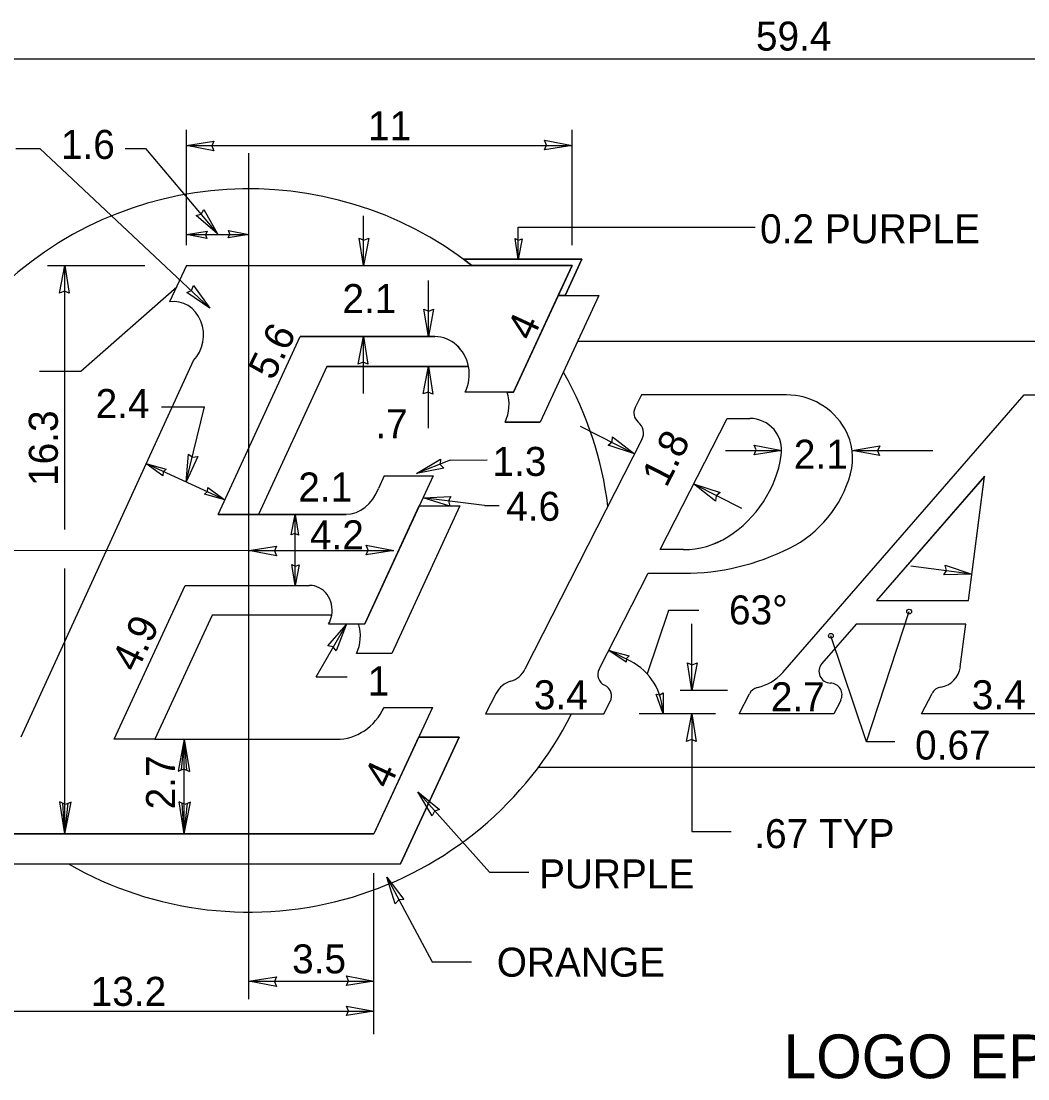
# Model space of a CAD drawing. Extents: x 10268197 to 10269179, y 2141503 to 2142677.
# Drawn here: x 10268684.39 to 10268704.22, y 2142077.2 to 2142098.03 of the extents above; entities that cross this region are included whole.
import ezdxf

# ---------------------------------------------------------------- set-up
doc = ezdxf.new("R2010")
doc.units = 0
doc.layers.add('Default', color=7, linetype='Continuous')
doc.layers.add('TextDetails', color=7, linetype='Continuous')

msp = doc.modelspace()

# ---------------------------------------------------------------- linework, layer by layer
at = {"layer": 'Default'}
for p, q in [((10268679.858, 2142097.295), (10268720.621, 2142097.295)), ((10268687.644, 2142093.619), (10268687.644, 2142095.89)), ((10268695.243, 2142093.619), (10268695.243, 2142095.89)), ((10268687.644, 2142095.584), (10268695.243, 2142095.584)), ((10268686.439, 2142095.525), (10268686.841, 2142095.525)), ((10268686.841, 2142095.525), (10268688.255, 2142093.844)), ((10268688.878, 2142087.607), (10268688.878, 2142095.433)), ((10268691.134, 2142093.218), (10268691.134, 2142094.201)), ((10268694.183, 2142093.342), (10268694.183, 2142093.975)), ((10268694.183, 2142093.975), (10268698.851, 2142093.975)), ((10268687.644, 2142093.831), (10268688.878, 2142093.831)), ((10268693.268, 2142093.218), (10268693.105, 2142093.342)), ((10268693.105, 2142093.342), (10268695.436, 2142093.342)), ((10268693.105, 2142093.342), (10268695.436, 2142093.342)), ((10268695.436, 2142093.342), (10268695.107, 2142092.629)), ((10268695.436, 2142093.342), (10268695.107, 2142092.629)), ((10268684.906, 2142093.218), (10268686.824, 2142093.218)), ((10268685.25, 2142088.019), (10268685.25, 2142093.218)), ((10268687.644, 2142093.218), (10268687.315, 2142092.505)), ((10268687.644, 2142093.218), (10268695.243, 2142093.218)), ((10268695.243, 2142093.218), (10268693.268, 2142093.218)), ((10268695.243, 2142093.218), (10268694.091, 2142090.725)), ((10268694.971, 2142092.629), (10268695.243, 2142093.218)), ((10268692.412, 2142091.819), (10268692.412, 2142092.925)), ((10268685.565, 2142091.137), (10268687.454, 2142092.8)), ((10268694.091, 2142090.725), (10268694.971, 2142092.629)), ((10268695.77, 2142092.629), (10268694.617, 2142090.135)), ((10268695.77, 2142092.629), (10268694.617, 2142090.135)), ((10268694.971, 2142092.629), (10268695.77, 2142092.629)), ((10268694.971, 2142092.629), (10268695.77, 2142092.629)), ((10268694.971, 2142092.629), (10268695.77, 2142092.629)), ((10268695.107, 2142092.629), (10268694.971, 2142092.629)), ((10268688.27, 2142088.318), (10268689.885, 2142091.819)), ((10268688.27, 2142088.318), (10268689.885, 2142091.819)), ((10268688.27, 2142088.318), (10268689.885, 2142091.819)), ((10268689.885, 2142091.819), (10268692.542, 2142091.819)), ((10268689.885, 2142091.819), (10268692.542, 2142091.819)), ((10268690.384, 2142091.819), (10268689.885, 2142091.819)), ((10268689.885, 2142091.819), (10268692.542, 2142091.819)), ((10268689.885, 2142091.819), (10268692.542, 2142091.819)), ((10268692.542, 2142091.819), (10268690.384, 2142091.819)), ((10268691.134, 2142090.698), (10268691.134, 2142091.819)), ((10268720.621, 2142091.721), (10268695.35, 2142091.721)), ((10268684.389, 2142083.937), (10268687.785, 2142091.349)), ((10268690.414, 2142091.229), (10268689.068, 2142088.318)), ((10268690.414, 2142091.229), (10268689.068, 2142088.318)), ((10268690.414, 2142091.229), (10268689.068, 2142088.318)), ((10268693.204, 2142091.229), (10268690.414, 2142091.229)), ((10268690.414, 2142091.229), (10268693.204, 2142091.229)), ((10268693.204, 2142091.229), (10268690.414, 2142091.229)), ((10268693.204, 2142091.229), (10268690.912, 2142091.229)), ((10268692.412, 2142090.014), (10268692.412, 2142091.229)), ((10268684.749, 2142091.137), (10268685.565, 2142091.137)), ((10268694.091, 2142090.725), (10268693.14, 2142090.725)), ((10268693.964, 2142090.725), (10268694.091, 2142090.725)), ((10268696.612, 2142090.673), (10268696.485, 2142090.424)), ((10268699.465, 2142090.673), (10268696.612, 2142090.673)), ((10268699.394, 2142085.202), (10268704.15, 2142090.673)), ((10268704.15, 2142090.673), (10268704.987, 2142090.673)), ((10268687.155, 2142090.434), (10268688, 2142090.434)), ((10268687.637, 2142088.957), (10268688, 2142090.434)), ((10268696.978, 2142087.623), (10268698.296, 2142090.208)), ((10268696.978, 2142087.623), (10268698.296, 2142090.207)), ((10268698.296, 2142090.208), (10268698.745, 2142090.208)), ((10268698.296, 2142090.207), (10268698.745, 2142090.207)), ((10268693.922, 2142090.135), (10268694.617, 2142090.135)), ((10268694.617, 2142090.135), (10268693.922, 2142090.135)), ((10268695.402, 2142090.057), (10268696.476, 2142089.509)), ((10268696.62, 2142089.793), (10268694.315, 2142085.267)), ((10268698.269, 2142089.579), (10268699.373, 2142089.579)), ((10268700.76, 2142089.579), (10268702.349, 2142089.579)), ((10268688.402, 2142088.604), (10268686.848, 2142089.32)), ((10268692.842, 2142089.387), (10268692.177, 2142089.122)), ((10268692.842, 2142089.387), (10268693.568, 2142089.391)), ((10268692.507, 2142089.075), (10268691.162, 2142086.163)), ((10268691.542, 2142089.075), (10268691.428, 2142088.827)), ((10268691.542, 2142089.075), (10268692.507, 2142089.075)), ((10268697.639, 2142088.918), (10268698.579, 2142088.439)), ((10268703.37, 2142089.067), (10268701.243, 2142086.621)), ((10268703.37, 2142089.066), (10268701.243, 2142086.621)), ((10268703.051, 2142086.621), (10268703.37, 2142089.067)), ((10268703.051, 2142086.621), (10268703.37, 2142089.066)), ((10268691.162, 2142086.163), (10268692.234, 2142088.485)), ((10268693.033, 2142088.485), (10268691.69, 2142085.575)), ((10268693.033, 2142088.485), (10268691.69, 2142085.575)), ((10268692.234, 2142088.485), (10268693.033, 2142088.485)), ((10268692.234, 2142088.485), (10268693.033, 2142088.485)), ((10268693.517, 2142088.494), (10268692.307, 2142088.643)), ((10268693.517, 2142088.494), (10268693.805, 2142088.495)), ((10268688.27, 2142088.318), (10268690.791, 2142088.318)), ((10268690.791, 2142088.318), (10268688.27, 2142088.318)), ((10268689.068, 2142088.318), (10268688.27, 2142088.318)), ((10268688.27, 2142088.318), (10268690.791, 2142088.318)), ((10268690.791, 2142088.318), (10268688.27, 2142088.318)), ((10268688.769, 2142088.318), (10268689.569, 2142088.318)), ((10268689.79, 2142086.919), (10268689.79, 2142088.318)), ((10268688.878, 2142087.607), (10268681.752, 2142087.596)), ((10268688.878, 2142078.769), (10268688.878, 2142087.607)), ((10268688.878, 2142087.607), (10268691.729, 2142087.607)), ((10268697.439, 2142087.623), (10268696.978, 2142087.623)), ((10268697.439, 2142087.623), (10268696.978, 2142087.623)), ((10268685.25, 2142082.021), (10268685.25, 2142087.253)), ((10268703.12, 2142087.142), (10268701.916, 2142087.298)), ((10268695.777, 2142085.267), (10268696.741, 2142087.157)), ((10268696.741, 2142087.157), (10268697.439, 2142087.157)), ((10268686.222, 2142083.887), (10268687.622, 2142086.919)), ((10268686.222, 2142083.887), (10268687.622, 2142086.919)), ((10268687.622, 2142086.919), (10268690.073, 2142086.919)), ((10268687.622, 2142086.919), (10268690.073, 2142086.919)), ((10268701.243, 2142086.621), (10268703.051, 2142086.621)), ((10268701.243, 2142086.621), (10268703.051, 2142086.621)), ((10268697.144, 2142086.422), (10268696.722, 2142085.177)), ((10268697.743, 2142086.422), (10268697.144, 2142086.422)), ((10268701.046, 2142083.836), (10268701.886, 2142086.402)), ((10268688.152, 2142086.329), (10268687.021, 2142083.887)), ((10268688.152, 2142086.329), (10268687.021, 2142083.887)), ((10268690.508, 2142086.329), (10268688.152, 2142086.329)), ((10268690.508, 2142086.329), (10268688.152, 2142086.329)), ((10268690.201, 2142085.115), (10268690.793, 2142086.14)), ((10268690.447, 2142086.163), (10268691.162, 2142086.163)), ((10268691.037, 2142086.163), (10268691.162, 2142086.163)), ((10268697.605, 2142084.851), (10268697.605, 2142086.163)), ((10268700.84, 2142086.154), (10268700.165, 2142085.378)), ((10268703.003, 2142086.154), (10268700.84, 2142086.154)), ((10268702.893, 2142085.314), (10268703.003, 2142086.154)), ((10268701.046, 2142083.836), (10268700.342, 2142085.926)), ((10268691.69, 2142085.575), (10268690.994, 2142085.575)), ((10268691.69, 2142085.575), (10268690.994, 2142085.575)), ((10268696.396, 2142085.423), (10268695.969, 2142085.642)), ((10268690.201, 2142085.115), (10268690.809, 2142085.115)), ((10268693.748, 2142084.796), (10268693.539, 2142084.385)), ((10268698.304, 2142084.851), (10268697.372, 2142084.851)), ((10268698.536, 2142084.385), (10268698.739, 2142084.784)), ((10268702.13, 2142084.385), (10268702.337, 2142084.789)), ((10268695.867, 2142084.385), (10268695.994, 2142084.634)), ((10268700.538, 2142084.654), (10268700.4, 2142084.385)), ((10268692.493, 2142084.516), (10268691.34, 2142082.021)), ((10268691.542, 2142084.516), (10268692.493, 2142084.516)), ((10268693.539, 2142084.385), (10268695.867, 2142084.385)), ((10268698.071, 2142084.386), (10268696.566, 2142084.386)), ((10268697.605, 2142084.386), (10268697.605, 2142082.07)), ((10268700.4, 2142084.385), (10268698.536, 2142084.385)), ((10268704.459, 2142084.385), (10268702.13, 2142084.385)), ((10268692.219, 2142083.926), (10268691.34, 2142082.021)), ((10268693.019, 2142083.926), (10268691.866, 2142081.431)), ((10268691.866, 2142081.431), (10268693.019, 2142083.926)), ((10268692.219, 2142083.926), (10268693.019, 2142083.926)), ((10268693.019, 2142083.926), (10268692.219, 2142083.926)), ((10268687.021, 2142083.887), (10268686.222, 2142083.887)), ((10268687.021, 2142083.887), (10268686.222, 2142083.887)), ((10268687.021, 2142083.887), (10268690.603, 2142083.887)), ((10268687.602, 2142083.887), (10268687.48, 2142083.258)), ((10268687.602, 2142083.887), (10268687.539, 2142083.283)), ((10268687.602, 2142082.021), (10268687.602, 2142083.887)), ((10268687.602, 2142083.887), (10268687.703, 2142083.254)), ((10268687.602, 2142083.887), (10268687.644, 2142083.281)), ((10268701.604, 2142083.836), (10268701.046, 2142083.836)), ((10268687.48, 2142083.258), (10268687.592, 2142083.305)), ((10268687.592, 2142083.305), (10268687.703, 2142083.254)), ((10268694.582, 2142083.337), (10268716.35, 2142083.337)), ((10268685.25, 2142082.021), (10268685.15, 2142082.653)), ((10268685.26, 2142082.603), (10268685.15, 2142082.653)), ((10268685.25, 2142082.021), (10268685.372, 2142082.649)), ((10268685.372, 2142082.649), (10268685.26, 2142082.603)), ((10268687.602, 2142082.021), (10268687.502, 2142082.653)), ((10268687.612, 2142082.603), (10268687.502, 2142082.653)), ((10268687.602, 2142082.021), (10268687.724, 2142082.649)), ((10268687.724, 2142082.649), (10268687.612, 2142082.603)), ((10268692.206, 2142082.851), (10268693.615, 2142081.271)), ((10268685.25, 2142082.021), (10268685.208, 2142082.626)), ((10268685.25, 2142082.021), (10268685.313, 2142082.625)), ((10268687.602, 2142082.021), (10268687.56, 2142082.626)), ((10268687.602, 2142082.021), (10268687.666, 2142082.625)), ((10268682.288, 2142082.021), (10268691.34, 2142082.021)), ((10268691.34, 2142082.021), (10268683.678, 2142082.021)), ((10268697.605, 2142082.07), (10268698.381, 2142082.07)), ((10268683.405, 2142081.431), (10268691.866, 2142081.431)), ((10268683.405, 2142081.431), (10268691.866, 2142081.431)), ((10268691.34, 2142078.077), (10268691.34, 2142081.246)), ((10268693.615, 2142081.271), (10268694.39, 2142081.271)), ((10268691.597, 2142081.169), (10268692.484, 2142079.502)), ((10268692.484, 2142079.502), (10268693.26, 2142079.502)), ((10268688.878, 2142079.12), (10268691.34, 2142079.12)), ((10268682.313, 2142078.528), (10268691.34, 2142078.528))]:
    msp.add_line(p, q, dxfattribs=at)
for points in [[(10268687.644, 2142095.584), (10268688.188, 2142095.67), (10268688.147, 2142095.577), (10268688.184, 2142095.48)], [(10268695.243, 2142095.584), (10268694.699, 2142095.499), (10268694.74, 2142095.592), (10268694.703, 2142095.688)], [(10268688.255, 2142093.844), (10268687.839, 2142094.205), (10268687.937, 2142094.234), (10268687.987, 2142094.325)], [(10268688.878, 2142093.831), (10268688.469, 2142093.767), (10268688.5, 2142093.836), (10268688.472, 2142093.909)], [(10268687.644, 2142093.831), (10268688.051, 2142093.895), (10268688.021, 2142093.825), (10268688.049, 2142093.753)], [(10268691.134, 2142093.218), (10268691.048, 2142093.762), (10268691.141, 2142093.721), (10268691.238, 2142093.758)], [(10268694.183, 2142093.342), (10268694.119, 2142093.75), (10268694.189, 2142093.719), (10268694.261, 2142093.748)], [(10268693.105, 2142093.342), (10268693.268, 2142093.218), (10268695.243, 2142093.218), (10268694.971, 2142092.629), (10268695.107, 2142092.629), (10268695.436, 2142093.342)], [(10268685.25, 2142093.218), (10268685.336, 2142092.674), (10268685.243, 2142092.715), (10268685.146, 2142092.678)], [(10268688.109, 2142092.378), (10268687.654, 2142092.688), (10268687.747, 2142092.728), (10268687.786, 2142092.824)], [(10268692.412, 2142091.819), (10268692.326, 2142092.363), (10268692.42, 2142092.322), (10268692.516, 2142092.359)], [(10268691.134, 2142091.819), (10268691.22, 2142091.275), (10268691.127, 2142091.316), (10268691.03, 2142091.279)], [(10268692.412, 2142091.229), (10268692.498, 2142090.685), (10268692.405, 2142090.726), (10268692.308, 2142090.689)], [(10268696.476, 2142089.509), (10268695.952, 2142089.68), (10268696.031, 2142089.745), (10268696.042, 2142089.848)], [(10268699.373, 2142089.579), (10268698.829, 2142089.493), (10268698.87, 2142089.587), (10268698.833, 2142089.683)], [(10268700.76, 2142089.579), (10268701.304, 2142089.665), (10268701.264, 2142089.572), (10268701.301, 2142089.475)], [(10268686.848, 2142089.32), (10268687.246, 2142089.208), (10268687.188, 2142089.157), (10268687.183, 2142089.08)], [(10268687.637, 2142088.957), (10268687.683, 2142089.506), (10268687.764, 2142089.444), (10268687.867, 2142089.457)], [(10268692.177, 2142089.122), (10268692.651, 2142089.403), (10268692.647, 2142089.301), (10268692.718, 2142089.225)], [(10268697.639, 2142088.918), (10268698.162, 2142088.747), (10268698.083, 2142088.683), (10268698.072, 2142088.58)], [(10268688.402, 2142088.604), (10268688.004, 2142088.717), (10268688.061, 2142088.767), (10268688.066, 2142088.845)], [(10268692.307, 2142088.643), (10268692.857, 2142088.67), (10268692.806, 2142088.581), (10268692.833, 2142088.481)], [(10268689.79, 2142088.318), (10268689.854, 2142087.91), (10268689.784, 2142087.941), (10268689.712, 2142087.913)], [(10268688.878, 2142087.607), (10268689.422, 2142087.692), (10268689.381, 2142087.599), (10268689.418, 2142087.502)], [(10268691.729, 2142087.607), (10268691.185, 2142087.521), (10268691.226, 2142087.614), (10268691.189, 2142087.711)], [(10268689.79, 2142086.919), (10268689.725, 2142087.327), (10268689.795, 2142087.296), (10268689.868, 2142087.324)], [(10268703.12, 2142087.142), (10268702.569, 2142087.127), (10268702.622, 2142087.214), (10268702.597, 2142087.315)], [(10268690.793, 2142086.14), (10268690.595, 2142085.626), (10268690.535, 2142085.709), (10268690.433, 2142085.725)], [(10268695.97, 2142085.636), (10268696.37, 2142085.533), (10268696.314, 2142085.481), (10268696.311, 2142085.403)], [(10268697.605, 2142084.851), (10268697.519, 2142085.395), (10268697.612, 2142085.354), (10268697.709, 2142085.391)], [(10268697.037, 2142084.389), (10268696.899, 2142084.778), (10268696.973, 2142084.761), (10268697.04, 2142084.801)], [(10268697.605, 2142084.386), (10268697.691, 2142083.842), (10268697.598, 2142083.883), (10268697.501, 2142083.845)], [(10268692.206, 2142082.851), (10268692.632, 2142082.502), (10268692.535, 2142082.471), (10268692.488, 2142082.379)], [(10268691.597, 2142081.169), (10268691.928, 2142080.729), (10268691.827, 2142080.722), (10268691.759, 2142080.643)], [(10268688.878, 2142079.12), (10268689.422, 2142079.206), (10268689.381, 2142079.113), (10268689.418, 2142079.016)], [(10268691.34, 2142079.12), (10268690.796, 2142079.034), (10268690.837, 2142079.128), (10268690.8, 2142079.224)], [(10268691.34, 2142078.528), (10268690.796, 2142078.442), (10268690.837, 2142078.535), (10268690.8, 2142078.632)]]:
    msp.add_lwpolyline(points, close=True, dxfattribs=at)
msp.add_lwpolyline([(10268684.287, 2142095.528), (10268684.754, 2142095.528), (10268688.109, 2142092.378)], dxfattribs=at)
for centre in [(10268701.885, 2142086.402), (10268700.342, 2142085.925)]:
    msp.add_circle(centre, 0.0466, dxfattribs=at)
for centre, radius, start, end in [((10268688.878, 2142087.607), 7.125, 51.9618, 218.2529), ((10268688.878, 2142087.607), 7.125, 7.0123, 29.4243), ((10268699.465, 2142089.345), 1.327, 29.4315, 90), ((10268696.693, 2142090.318), 0.233, 152.9784, 231.1602), ((10268698.744, 2142089.578), 0.629, 351.076, 90), ((10268698.744, 2142089.579), 0.629, 351.076, 90), ((10268696.371, 2142089.919), 0.279, 333.0027, 51.1602), ((10268699.607, 2142089.425), 1.164, 344.7074, 29.4315), ((10268697.065, 2142089.842), 2.329, 302.4206, 351.076), ((10268697.065, 2142089.842), 2.329, 302.4206, 351.076), ((10268698.483, 2142089.732), 2.329, 296.6431, 344.7074), ((10268697.439, 2142089.253), 1.63, 270, 302.4206), ((10268697.439, 2142089.252), 1.63, 270, 302.4206), ((10268697.439, 2142091.814), 4.657, 270, 296.6431), ((10268695.867, 2142084.386), 1.164, 0, 62.9941), ((10268700.34, 2142085.226), 0.233, 138.9824, 268.6869), ((10268693.9, 2142085.478), 0.466, 286.4317, 332.9959), ((10268695.985, 2142085.161), 0.233, 152.9884, 244.7832), ((10268698.69, 2142085.814), 0.931, 282.7162, 318.9966), ((10268702.432, 2142085.373), 0.466, 279.2397, 352.5632), ((10268694.163, 2142084.584), 0.466, 106.4317, 152.9742), ((10268695.786, 2142084.74), 0.233, 333.0239, 64.7832), ((10268700.329, 2142084.76), 0.233, 332.9784, 88.6869), ((10268698.947, 2142084.678), 0.233, 102.7162, 153.0239), ((10268702.544, 2142084.684), 0.233, 99.2397, 153.0239), ((10268688.878, 2142087.607), 7.125, 240.0889, 333.1198)]:
    msp.add_arc(centre, radius, start, end, dxfattribs=at)
for centre, major_axis, ratio, start_param, end_param in [((10268687.393, 2142091.847), (0, 0.665), 0.889671, 3.865417, 6.41824), ((10268692.541, 2142091.072), (0, 0.747), 0.906667, 4.924065, 6.283185), ((10268692.541, 2142091.072), (0, 0.747), 0.906667, 4.924772, 6.283185), ((10268692.541, 2142091.072), (0, 0.747), 0.906667, 4.924772, 6.283185), ((10268692.541, 2142091.072), (0, 0.747), 0.906667, 4.924772, 6.283185), ((10268692.541, 2142091.072), (0, 0.747), 0.906667, 4.228038, 4.924065), ((10268693.324, 2142090.483), (0, 0.747), 0.906667, 4.227342, 5.041732), ((10268693.324, 2142090.483), (0, 0.747), 0.906667, 4.227342, 5.041732), ((10268690.792, 2142089.253), (0, 0.933), 0.764971, 3.141593, 4.241405), ((10268690.072, 2142086.428), (0, 0.491), 0.906667, 4.510784, 6.283185), ((10268690.072, 2142086.428), (0, 0.491), 0.906667, 4.510784, 6.283185), ((10268690.072, 2142086.428), (0, 0.491), 0.906667, 4.144801, 4.510784), ((10268690.396, 2142085.923), (0, 0.747), 0.906667, 4.227342, 5.041732), ((10268690.396, 2142085.923), (0, 0.747), 0.906667, 4.227342, 5.041732), ((10268690.603, 2142085.053), (0, 1.166), 0.906667, 3.141593, 4.233038)]:
    msp.add_ellipse(centre, major_axis=major_axis, ratio=ratio, start_param=start_param, end_param=end_param, dxfattribs=at)

# ---------------------------------------------------------------- texts
for s, height, p in [('59.4', 0.5717, (10268698.866, 2142097.454)), ('11', 0.5717, (10268691.224, 2142095.687)), ('1.6', 0.5717, (10268685.172, 2142095.32)), ('0.2 PURPLE', 0.5717, (10268698.948, 2142093.658)), ('2.1', 0.5717, (10268690.719, 2142092.282)), ('2.4', 0.5717, (10268685.857, 2142090.215)), ('.7', 0.5717, (10268691.367, 2142089.818)), ('2.1', 0.5717, (10268699.613, 2142089.216)), ('1.3', 0.5717, (10268693.675, 2142089.075)), ('2.1', 0.5717, (10268689.849, 2142088.571)), ('4.6', 0.5717, (10268693.945, 2142088.191)), ('4.2', 0.5717, (10268690.079, 2142087.628)), ('63°', 0.5717, (10268698.335, 2142086.15)), ('1', 0.572, (10268691.218, 2142084.749)), ('3.4', 0.5717, (10268694.49, 2142084.478)), ('2.7', 0.5717, (10268699.159, 2142084.438)), ('3.4', 0.5717, (10268703.119, 2142084.478)), ('0.67', 0.5717, (10268702.002, 2142083.487)), ('.67 TYP', 0.5717, (10268698.833, 2142081.742)), ('PURPLE', 0.5717, (10268694.593, 2142080.949)), ('3.5', 0.5717, (10268689.727, 2142079.275)), ('ORANGE', 0.5717, (10268693.76, 2142079.21)), ('13.2', 0.5717, (10268685.759, 2142078.635))]:
    msp.add_text(s, height=height, dxfattribs=at).set_placement(p)
for s, height, rotation, p in [('4', 0.572, 65.0602, (10268694.455, 2142091.711)), ('5.6', 0.5717, 64.0244, (10268689.352, 2142090.936)), ('16.3', 0.5717, 90, (10268685.112, 2142088.878)), ('1.8', 0.5717, 62.9907, (10268697.102, 2142088.828)), ('4.9', 0.5717, 64.0244, (10268686.661, 2142085.184)), ('2.7', 0.5717, 90, (10268687.422, 2142082.506)), ('4', 0.572, 65.0602, (10268691.637, 2142082.886))]:
    msp.add_text(s, height=height, rotation=rotation, dxfattribs=at).set_placement(p)
at = {"layer": 'TextDetails'}
msp.add_text('LOGO EP-10.4R', height=0.8624, dxfattribs=at).set_placement((10268699.412, 2142077.209))

doc.saveas('drawing.dxf')
